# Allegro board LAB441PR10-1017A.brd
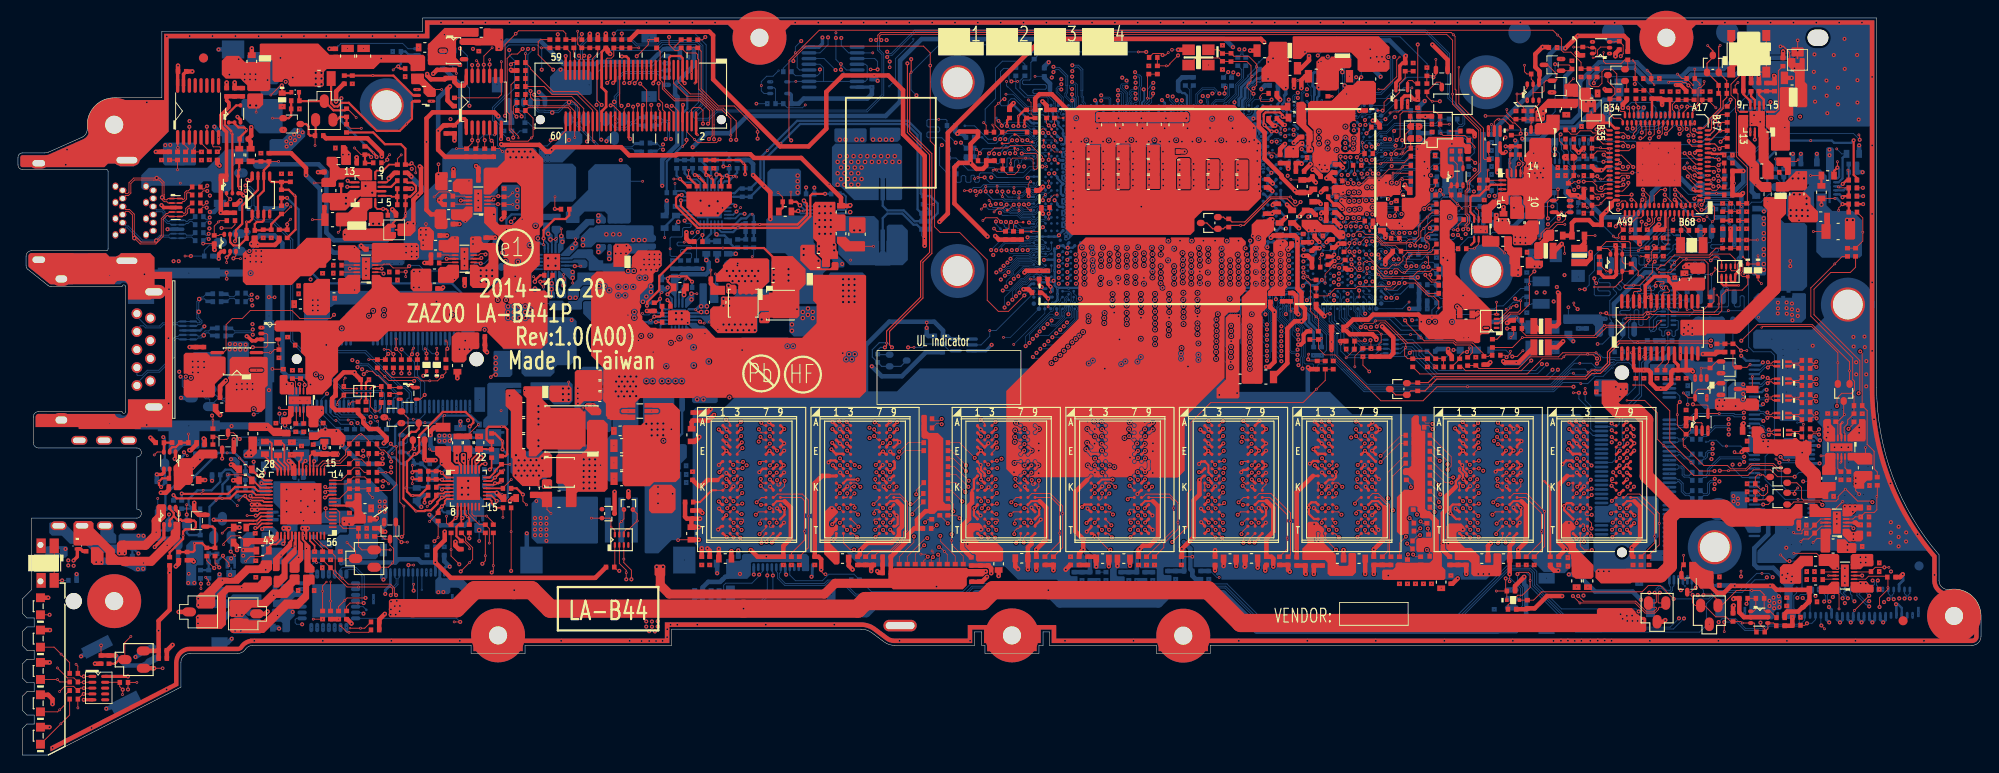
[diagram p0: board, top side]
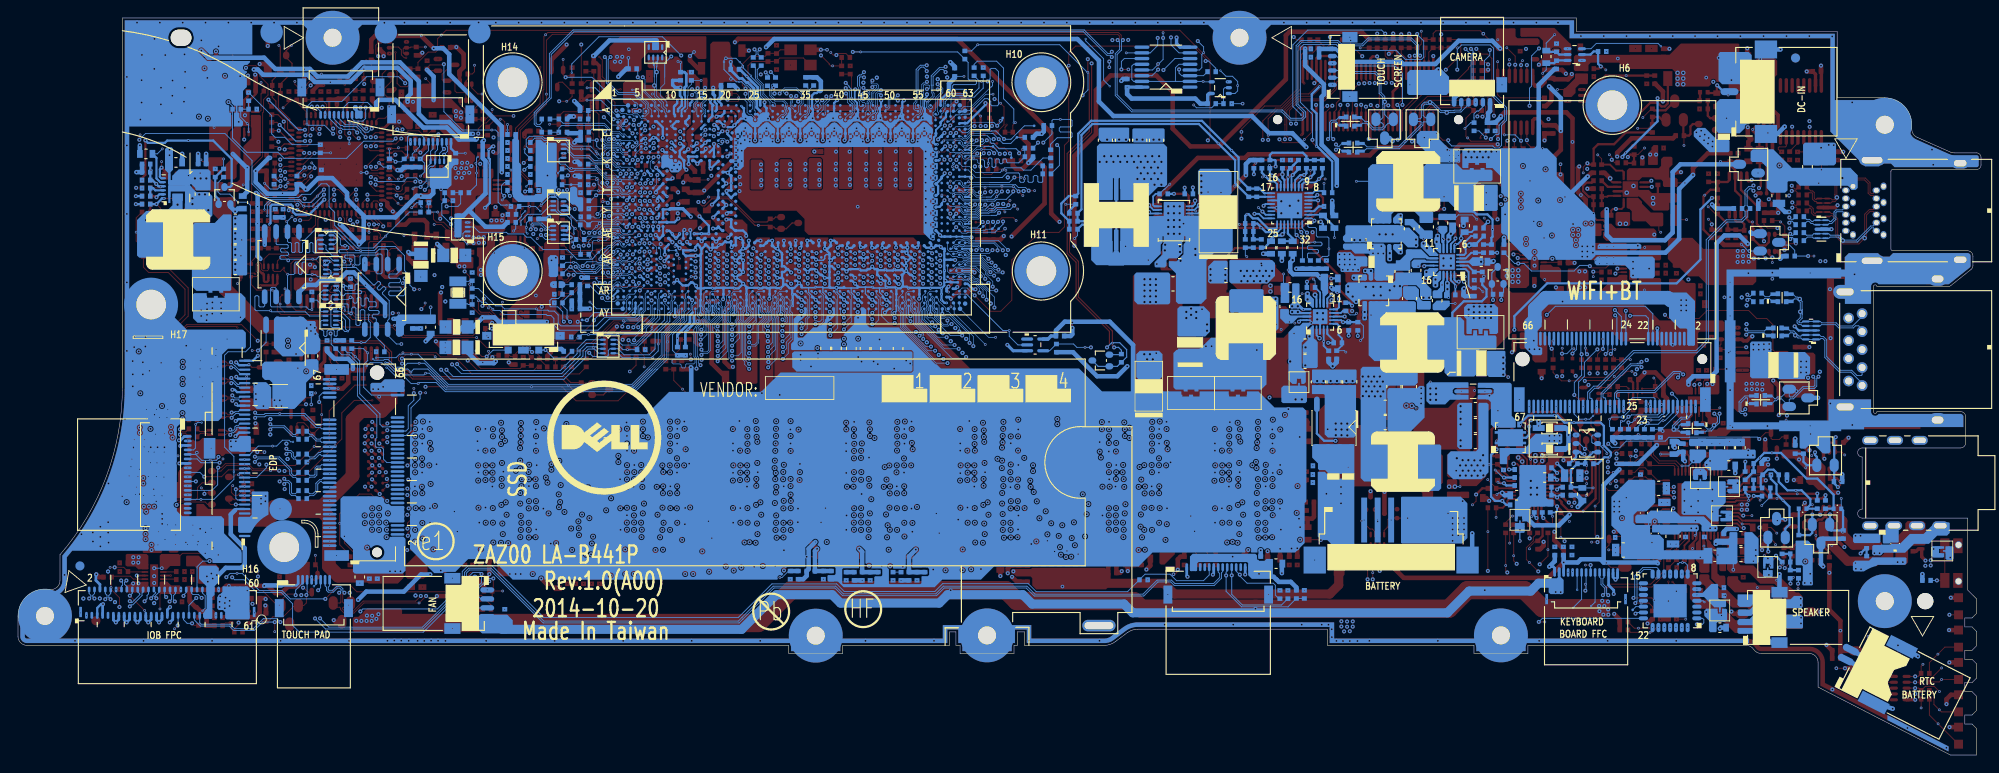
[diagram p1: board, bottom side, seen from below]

Outline 218.31 x 82 mm; copper layers: TOP, GND1, IN1, GND2, IN2, IN3, VCC, IN4, GND3, BOTTOM. Coordinates in mm from the lower left corner of the outline.
Outline path: 0,66.49 arc(0.15,66.84) 0.5,66.99 2.99,66.99 arc(3.2,67.01) 3.39,67.08 7.11,68.73 arc(7.54,69.09) 7.7,69.64 7.7,70.12 arc(8.58,72.24) 10.7,73.12 16,73.12 16,80.5 45,80.5 45,82 206.7,82 206.7,40.92 arc(208.49,30.98) 213.64,22.28 213.64,19.41 arc(213.99,18.65) 214.81,18.43 arc(217.25,17.76) 218.31,15.47 218.31,13.2 arc(218.02,12.49) 217.31,12.2 132.59,12.2 132.59,11.3 126.59,11.3 126.59,12.2 114.7,12.2 114.7,13.7 114,13.7 114,12.2 113.54,12.2 113.54,11.3 107.54,11.3 107.54,12.2 107.18,12.2 107.18,13.7 106.38,13.7 106.38,12.2 97.49,12.2 arc(96.86,12.3) 96.29,12.6 94.96,13.6 arc(94.39,13.9) 93.76,14 72.7,14 72.7,12.2 56.39,12.2 56.39,11.3 50.39,11.3 50.39,12.2 26.12,12.2 arc(25.64,12.08) 25.28,11.75 arc(24.92,11.42) 24.44,11.3 19.12,11.3 arc(18.41,11.01) 18.12,10.3 18.12,7.56 3.4,0 0.5,0 0.5,2.95 1,3.45 1.8,3.45 1.8,4.45 1,4.45 0.5,4.95 0.5,6.55 1,7.05 1.8,7.05 1.8,8.05 1,8.05 0.5,8.55 0.5,10.15 1,10.65 1.8,10.65 1.8,11.65 1,11.65 0.5,12.15 0.5,13.75 1,14.25 1.8,14.25 1.8,15.25 1,15.25 0.5,15.75 0.5,17.38 1.5,18.38 1.5,26.36 13.22,26.36 arc(13.72,26.86) 13.22,27.36 13.22,33.16 arc(13.72,33.66) 13.22,34.16 2.3,34.16 arc(1.88,34.34) 1.7,34.76 1.7,37.61 arc(1.88,38.03) 2.3,38.21 11.57,38.21 arc(11.77,38.01) 11.97,38.21 11.97,52.11 arc(11.77,52.31) 11.57,52.11 3.68,52.11 arc(3.51,52.14) 3.36,52.22 1.09,54.04 arc(0.95,54.21) 0.9,54.43 0.9,55.5 arc(1.08,55.93) 1.5,56.1 9.82,56.1 arc(9.96,56.16) 10.02,56.3 10.02,64.94 arc(9.96,65.08) 9.82,65.14 0.5,65.14 arc(0.15,65.29) 0,65.64 0,66.49

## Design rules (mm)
constraint set DEFAULT: min track width 0.102
net group 20: nets +RTCVCC N48756972
net group CLK_TP: nets CLK_TP_SIO DAT_TP_SIO
net group DDR-RESET: nets DDR3_DRAMRST# H_DRAMRST#
net group DDRA-CKE: nets DDR_A_CKE0 DDR_A_CKE1
net group DDRB-CKE: nets DDR_B_CKE0 DDR_B_CKE1
net group DIFFPAIR5: nets DMIC_CLK_CODEC DMIC_DAT_CODEC
net group DIFFPAIR23: nets CLK_SMB DAT_SMB
net group DIFFPAIR27: nets PCH_SMBCLK PCH_SMBDATA
net group DIFFPAIR44: nets SML1_SMBCLK SML1_SMBDAT
net group DMI_RCOMP: nets PCH_OPIRCOMP PROC_OPI_COMP
net group HOST-CLK: nets CLK_PCIE_MSATA CLK_PCIE_MSATA#
net group SML0CLK: nets SML0CLK SML0DATA
net group 5: nets CPU_XDP_TDI CPU_XDP_TDO CPU_XDP_TMS CPU_XDP_TRST# DSWODVREN PCH_DPWROK PCH_INTVRMEN PCH_JTAG_TCK PCH_JTAG_TDI PCH_JTAG_TDO PCH_JTAG_TMS PCH_RSMRST# SYS_PWROK SYS_RESET#
net group 8: nets 1.05VS_VCCST_PG H_CATERR# H_PROCHOT# H_PROCHOT#_R XDP_BPM1#
net group 12: nets +V1.05S_ASATA3PLL +V1.05S_AUSB3PLL PCIE_RCOMP SATA_RCOMP
net group 15: nets DISP_CLK_AUXP_CONN DISP_DAT_AUXN_CONN PCH_DP_CLK PCH_DP_DAT PCH_RTCRST# PCH_RTCX1 PCH_RTCX2 PCH_SRTCRST# SDIO_CLK SUSCLK
net group 18: nets CLK_LPC_DEBUG CLK_PCI_MEC CLK_PCIE_MMI CLK_PCIE_MMI# CLK_PCIE_WLAN CLK_PCIE_WLAN# CLKOUT_LPC0 CLKOUT_LPC1 EDP_AUXN EDP_AUXN_C EDP_AUXN_CONN EDP_AUXP EDP_AUXP_C EDP_AUXP_CONN EDP_TXN_P0 EDP_TXN_P0_C EDP_TXN_P0_CONN EDP_TXN_P1_C EDP_TXN_P1_CONN EDP_TXN_P2 EDP_TXN_P2_C EDP_TXN_P2_CONN EDP_TXN_P3 EDP_TXN_P3_C EDP_TXN_P3_CONN EDP_TXP_P0 EDP_TXP_P0_C EDP_TXP_P0_CONN EDP_TXP_P1_C EDP_TXP_P1_CONN EDP_TXP_P2 EDP_TXP_P2_C EDP_TXP_P2_CONN EDP_TXP_P3 EDP_TXP_P3_C EDP_TXP_P3_CONN H_CPU_SVIDALRT# H_CPU_SVIDCLK H_CPU_SVIDDAT PCH_DP_AUXN PCH_DP_AUXN_C PCH_DP_AUXP PCH_DP_AUXP_C PCH_DP_N0_C PCH_DP_N1 PCH_DP_N1_C PCH_DP_N2_C PCH_DP_N3 PCH_DP_N3_C PCH_DP_P0_C PCH_DP_P1 PCH_DP_P1_C PCH_DP_P2_C PCH_DP_P3 PCH_DP_P3_C PCIE_PRX_CARDTX_N1 PCIE_PRX_CARDTX_P1 PCIE_PRX_WLANTX_N4 PCIE_PRX_WLANTX_P4 PCIE_PTX_C_CARDRX_N1 PCIE_PTX_C_CARDRX_P1 PCIE_PTX_CARDRX_N1 PCIE_PTX_CARDRX_P1 PCIE_PTX_WLANRX_N4 PCIE_PTX_WLANRX_N4_C PCIE_PTX_WLANRX_P4 PCIE_PTX_WLANRX_P4_C SATA_RN2/PERN6_L1 SATA_RN2/PERN6_L1_C SATA_RN3/PERN6_L0_C SATA_RP2/PERP6_L1 SATA_RP2/PERP6_L1_C SATA_RP3/PERP6_L0_C SATA_TN2/PETN6_L1 SATA_TN2/PETN6_L1_C SATA_TN3/PETN6_L0_C SATA_TP2/PETP6_L1 SATA_TP2/PETP6_L1_C SATA_TP3/PETP6_L0_C USB3TN1 USB3TP1 USB20_N0 USB20_N1 USB20_N1_CONN USB20_N2 USB20_N2_R USB20_N3 USB20_N3_CONN USB20_N4 USB20_N4_CONN USB20_P0 USB20_P1 USB20_P1_CONN USB20_P2 USB20_P2_R USB20_P3 USB20_P3_CONN USB20_P4 USB20_P4_CONN USBRBIAS XTAL24_IN XTAL24_OUT
net group 25: nets EDP_COM
net group ASYNCHRONOUS: nets H_THERMTRIP# NGFF_RST# PCH_PLTRST# PCH_PLTRST#_EC PLTRST#_XDP RESET_OUT# THERMATRIP2# XDP_BPM0# XDP_PWRGD
net group DDR-DQS: nets DDR_A_DQS0 DDR_A_DQS1 DDR_A_DQS2 DDR_A_DQS3 DDR_A_DQS4 DDR_A_DQS5 DDR_A_DQS6 DDR_A_DQS7 DDR_A_DQS#0 DDR_A_DQS#1 DDR_A_DQS#2 DDR_A_DQS#3 DDR_A_DQS#4 DDR_A_DQS#5 DDR_A_DQS#6 DDR_A_DQS#7 DDR_B_DQS0 DDR_B_DQS1 DDR_B_DQS2 DDR_B_DQS3 DDR_B_DQS4 DDR_B_DQS5 DDR_B_DQS6 DDR_B_DQS7 DDR_B_DQS#0 DDR_B_DQS#1 DDR_B_DQS#2 DDR_B_DQS#3 DDR_B_DQS#4 DDR_B_DQS#5 DDR_B_DQS#6 DDR_B_DQS#7
net group DDR-SINGLE: nets SM_RCOMP0 SM_RCOMP1 SM_RCOMP2
net group DDRA-CMD: nets DDR_A_BA0 DDR_A_BA1 DDR_A_BA2 DDR_A_CAS# DDR_A_MA0 DDR_A_MA1 DDR_A_MA2 DDR_A_MA3 DDR_A_MA4 DDR_A_MA5 DDR_A_MA6 DDR_A_MA7 DDR_A_MA8 DDR_A_MA9 DDR_A_MA10 DDR_A_MA11 DDR_A_MA12 DDR_A_MA13 DDR_A_MA14 DDR_A_MA15 DDR_A_RAS# DDR_A_WE#
net group DDRA-CTL: nets DDR_A_CS0# DDR_A_CS1# M_ODT0
net group DDRA-D0: nets DDR_A_D0 DDR_A_D1 DDR_A_D2 DDR_A_D3 DDR_A_D4 DDR_A_D5 DDR_A_D6 DDR_A_D7
net group DDRA-D1: nets DDR_A_D8 DDR_A_D9 DDR_A_D10 DDR_A_D11 DDR_A_D12 DDR_A_D13 DDR_A_D14 DDR_A_D15
net group DDRA-D2: nets DDR_A_D16 DDR_A_D17 DDR_A_D18 DDR_A_D19 DDR_A_D20 DDR_A_D21 DDR_A_D22 DDR_A_D23
net group DDRA-D3: nets DDR_A_D24 DDR_A_D25 DDR_A_D26 DDR_A_D27 DDR_A_D28 DDR_A_D29 DDR_A_D30 DDR_A_D31
net group DDRA-D4: nets DDR_A_D32 DDR_A_D33 DDR_A_D34 DDR_A_D35 DDR_A_D36 DDR_A_D37 DDR_A_D38 DDR_A_D39
net group DDRA-D5: nets DDR_A_D40 DDR_A_D41 DDR_A_D42 DDR_A_D43 DDR_A_D44 DDR_A_D45 DDR_A_D46 DDR_A_D47
net group DDRA-D6: nets DDR_A_D48 DDR_A_D49 DDR_A_D50 DDR_A_D51 DDR_A_D52 DDR_A_D53 DDR_A_D54 DDR_A_D55
net group DDRA-D7: nets DDR_A_D56 DDR_A_D57 DDR_A_D58 DDR_A_D59 DDR_A_D60 DDR_A_D61 DDR_A_D62 DDR_A_D63
net group DDRB-CMD: nets DDR_B_BA0 DDR_B_BA1 DDR_B_BA2 DDR_B_CAS# DDR_B_MA0 DDR_B_MA1 DDR_B_MA2 DDR_B_MA3 DDR_B_MA4 DDR_B_MA5 DDR_B_MA6 DDR_B_MA7 DDR_B_MA8 DDR_B_MA9 DDR_B_MA10 DDR_B_MA11 DDR_B_MA12 DDR_B_MA13 DDR_B_MA14 DDR_B_MA15 DDR_B_RAS# DDR_B_WE#
net group DDRB-CTL: nets DDR_B_CS0# DDR_B_CS1# M_ODT2
net group DDRB-D0: nets DDR_B_D0 DDR_B_D1 DDR_B_D2 DDR_B_D3 DDR_B_D4 DDR_B_D5 DDR_B_D6 DDR_B_D7
net group DDRB-D1: nets DDR_B_D8 DDR_B_D9 DDR_B_D10 DDR_B_D11 DDR_B_D12 DDR_B_D13 DDR_B_D14 DDR_B_D15
net group DDRB-D2: nets DDR_B_D16 DDR_B_D17 DDR_B_D18 DDR_B_D19 DDR_B_D20 DDR_B_D21 DDR_B_D22 DDR_B_D23
net group DDRB-D3: nets DDR_B_D24 DDR_B_D25 DDR_B_D26 DDR_B_D27 DDR_B_D28 DDR_B_D29 DDR_B_D30 DDR_B_D31
net group DDRB-D4: nets DDR_B_D32 DDR_B_D33 DDR_B_D34 DDR_B_D35 DDR_B_D36 DDR_B_D37 DDR_B_D38 DDR_B_D39
net group DDRB-D5: nets DDR_B_D40 DDR_B_D41 DDR_B_D42 DDR_B_D43 DDR_B_D44 DDR_B_D45 DDR_B_D46 DDR_B_D47
net group DDRB-D6: nets DDR_B_D48 DDR_B_D49 DDR_B_D50 DDR_B_D51 DDR_B_D52 DDR_B_D53 DDR_B_D54 DDR_B_D55
net group DDRB-D7: nets DDR_B_D56 DDR_B_D57 DDR_B_D58 DDR_B_D59 DDR_B_D60 DDR_B_D61 DDR_B_D62 DDR_B_D63
net group DIFFPAIR39: nets I2C1_SDA
net group ESD-NOCROSS-MOAT: nets CFG0 CFG1 CFG2 CFG3 CFG4 CFG5 CFG6 CFG7 CFG8 CFG9 CFG10 CFG11 CFG12 CFG13 CFG14 CFG15 CFG16 CFG17 CFG18 CFG19 MPCIE_RST# PCH_JTAG_TRST# SUSACK# USB_OC0# USB_OC1# USB_OC2#
net group I2C0_SCK_DSP: nets I2C0_SDA_DSP
net group I2C_6_18: nets I2C0_SCK I2C0_SCK_DSP I2C0_SDA I2C1_SCK
net group I2S: nets I2S_BIT_CLK I2S_BITCLK_AUDIO I2S_BITCLK_AUDIO_R I2S_RST# I2S_RST_AUDIO# I2S_RST_AUDIO#_R I2S_SDIN0 I2S_SDIN0_AUDIO I2S_SDOUT I2S_SDOUT_AUDIO I2S_SDOUT_AUDIO_R I2S_SYNC I2S_SYNC_AUDIO I2S_SYNC_AUDIO_R
net group PWR: nets +0.675VS +0.675VSP +1.5V_B+ +1.05VDX_MODPHY_D +1.5VS +1.05VS_VCCST +1.05VSP +1.5VSP +1.8VS +1.8VSP +1.35V_DDR +3.3VDX_SSD +3V_NFC +3V_PCH +3V_PCH_DSW +3VALWP +3VLP +3VS_AUDIO +3VS_CAM +3VS_CR +3VS_TP +3VS_TPM +3VS_TS +5V_USB_P1 +5VALWP +5VS +5VS_AUDIO +AVDD1 +DVDD +DVDDIO +INV_PWR_SRC +LCDVDD +MD_VREF_CA +MD_VREF_DQA +MD_VREF_DQB +PCH_VCCDSW +RTC_VCCSUS +RTCBATT +V1.05S_APLLOPI +V1.05S_AXCK_DCB +V1.05S_AXCK_DCB_L +V1.05S_AXCK_LCPLL +V1.05S_AXCK_LCPLL_L +V1.05VS_VCCHSIO +VCCIO_OUT +VCCIOA_OUT +VS_LPSS_SDIO
net group SATA: nets SATA_RN3/PERN6_L0 SATA_RP3/PERP6_L0 SATA_TN3/PETN6_L0 SATA_TP3/PETP6_L0
net group SDIO_6_18: nets SDIO_CMD SDIO_D0 SDIO_D1 SDIO_D2 SDIO_D3
net group SENSE: nets VCCSENSE VCCSENSE_R VSSSENSE
net group SPI: nets PCH_SPI_CLK PCH_SPI_CLK_TPM PCH_SPI_CS0# PCH_SPI_CS1# PCH_SPI_CS2# PCH_SPI_IO2 PCH_SPI_IO3 PCH_SPI_SI PCH_SPI_SI_TPM PCH_SPI_SO PCH_SPI_SO_TPM SPI_CLK_ROM SPI_CLK_VROM SPI_IO2_ROM SPI_IO2_VROM SPI_IO3_ROM SPI_IO3_VROM SPI_SI_ROM SPI_SI_VROM SPI_SO_ROM SPI_SO_VROM
net group SVID: nets VR_SVID_ALRT# VR_SVID_CLK VR_SVID_DAT
net group UART_6_18: nets UART1_CTS# UART1_CTS#_NGFF UART1_RTS# UART1_RTS#_NGFF UART1_RXD UART1_RXD_NGFF UART1_TXD UART1_TXD_NGFF
net group USB30: nets USB3RN0 USB3RN1 USB3RN1_RC_CON USB3RP0 USB3RP1 USB3RP1_RC_CON USB3TN0 USB3TN1_C USB3TN1_RC_CON USB3TP0 USB3TP1_C USB3TP1_RC_CON
nets with their own width: min track width 0.102; nets JACK_PLUG_DL# NB_MUTE#
nets with their own width: min track width 0.127; nets REM_DIODE1_N REM_DIODE1_P REM_DIODE2_N REM_DIODE2_P REM_DIODE3_N REM_DIODE3_P REM_DIODE4_N REM_DIODE4_P
nets with their own width: min track width 0.254; nets +3.3V_ALW_DEG +RTC_CELL_VBAT MIC1-VREFO
nets with their own width: min track width 0.381; nets CFG_RCOMP
nets with their own width: min track width 0.508; nets +1.05VS +1.8VS_AUDIO +3.3V_M +3V_ROM +3VALW_5085 +VCC_CORE AGND B+ GND GNDA_CHG N45904045 N49757206 V_DDR_REF_CA
nets with their own width: min track width 1.016; nets MIC1_L_L MIC1_R_L SPK_L+_C SPK_L-_C SPK_OUT_L+ SPK_OUT_L- SPK_OUT_R+ SPK_OUT_R- SPK_R+_C SPK_R-_C
nets with their own width: min track width 1.524; nets +1.05VDX_MODPHY
nets with their own width: min track width 2.032; nets +3VS_NGFF

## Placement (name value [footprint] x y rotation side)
C1  .47U_0402_10V6K  [C_0402]  139.29 51.33 270 top
C2  15P_0402_50V8J  [C_0402]  23.39 40.66 180 top
C3  15P_0402_50V8J  [C_0402]  19.77 44.47 90 top
C4  15P_0402_50V8J  [C_0402]  54.03 70.35 270 bottom
C5  15P_0402_50V8J  [C_0402]  73.61 78.56 0 bottom
C6  15P_0402_50V8J  [C_0402]  193.21 33.97 180 top
C7  15P_0402_50V8J  [C_0402]  188.31 18.88 0 top
C8  2.2U_0603_6.3V6K~D  [C_0603]  45.95 78.72 180 top
C218  2200P_0402_25V7K  [C_0402]  161.07 56.33 180 top
C219  0.1U_0402_10V7K  [C_0402]  166.91 55.94 0 top
C265  .1U_0402_16V7K~D  [C_0402]  20.66 44.47 90 top
C303  150U_B2_6.3VM_R35M  [C_B2]  21.71 43.38 180 bottom
C352  0.1U_0402_10V7K  [C_0402]  45.74 51.89 0 top
C355  2200P_0402_25V7K~D  [C_0402]  46.84 54.75 180 top
C375  0.1U_0402_25V6K~D  [C_0402]  46.45 22.25 90 bottom
C376  0.1U_0402_25V6K~D  [C_0402]  47.4 22.25 90 bottom
C377  0.1U_0402_25V6K~D  [C_0402]  45.5 22.25 90 bottom
C612  0.1U_0402_25V6K~D  [C_0402]  186.61 41.1 180 bottom
C613  0.1U_0402_25V6K~D  [C_0402]  188.94 44.83 90 top
C621  0.1U_0402_10V7K  [C_0402]  25.32 50.43 180 bottom
C623  0.1U_0402_10V7K  [C_0402]  25.32 51.39 180 bottom
C712  22U_0603_6.3V6M~D  [C_0603]  32.11 50.17 180 top
C713  0.1U_0402_10V7K  [C_0402]  51.01 46.55 0 top
C715  0.1U_0402_10V7K  [C_0402]  32.12 52.2 180 top
C716  22U_0603_6.3V6M~D  [C_0603]  48.86 44.04 270 top
C719  4.7U_0603_6.3V6K  [C_0603]  180.29 20.52 270 bottom
C720  .1U_0402_16V7K~D  [C_0402]  176.45 41.35 180 top
C721  0.01U_0402_16V7K~D  [C_0402]  176.45 40.4 180 top
C722  47P_0402_50V8J~D  [C_0402]  179.24 20.54 270 bottom
C723  4.7U_0603_6.3V6K  [C_0603]  185.32 52.21 90 top
C962  10U_0603_6.3V6M~D  [C_0603]  23.37 38.63 180 top
C963  .1U_0402_16V7K~D  [C_0402]  23.39 39.77 180 top
C1060  0.1U_0402_10V7K  [C_0402]  199.31 37.3 180 top
C1061  0.1U_0402_10V7K  [C_0402]  199.31 39.21 180 top
C1062  0.1U_0402_10V7K  [C_0402]  199.31 38.19 180 top
C1063  0.1U_0402_10V7K  [C_0402]  199.31 40.1 180 top
C1064  0.1U_0402_10V7K  [C_0402]  199.31 36.29 180 top
C1065  0.1U_0402_10V7K  [C_0402]  199.31 35.4 180 top
C1066  0.1U_0402_10V7K  [C_0402]  199.31 42 180 top
C1067  0.1U_0402_10V7K  [C_0402]  199.31 41.11 180 top
C1068  0.1U_0402_10V7K  [C_0402]  199.31 43.91 180 top
C1069  0.1U_0402_10V7K  [C_0402]  199.31 43.02 180 top
C1102  0.1U_0402_25V6K~D  [C_0402]  164.18 16.21 270 bottom
C1134  0.1U_0402_10V7K  [C_0402]  80.1 21.17 90 bottom
C1137  2200P_0402_25V7K~D  [C_0402]  185.51 42.83 270 top
C1138  2200P_0402_25V7K~D  [C_0402]  180.81 42.83 270 top
C1139  2200P_0402_25V7K~D  [C_0402]  179.93 42.83 270 top
C1140  0.1U_0402_10V7K  [C_0402]  184.24 52.2 90 top
C1141  0.1U_0402_10V7K  [C_0402]  183.94 45.21 90 bottom
C1142  2200P_0402_25V7K~D  [C_0402]  184.62 42.83 270 top
C1143  10U_0603_6.3V6M~D  [C_0603]  193.2 36.07 180 top
C1145  .1U_0402_16V7K~D  [C_0402]  193.21 34.93 180 top
C1158  1U_0402_6.3V6K~D  [C_0402]  204.93 27.51 0 top
C1159  0.1U_0402_10V7K  [C_0402]  199.15 17.05 0 top
C1160  1U_0402_6.3V6K~D  [C_0402]  41.29 52.85 0 top
C1161  0.1U_0402_10V7K  [C_0402]  204.18 23.2 0 top
C1162  1U_0402_6.3V6K~D  [C_0402]  204.93 24.59 0 top
C1163  2200P_0402_25V7K~D  [C_0402]  199.8 24.69 180 top
C1164  0.1U_0402_10V7K  [C_0402]  197.13 25.89 0 top
C1165  1U_0402_6.3V6K~D  [C_0402]  201.26 37.09 90 top
C1166  1U_0402_6.3V6K~D  [C_0402]  39.67 56.28 180 top
C1167  2200P_0402_25V7K~D  [C_0402]  35.98 53.61 180 top
C1169  1U_0402_6.3V6K~D  [C_0402]  29.51 42.01 90 top
C1199  1U_0402_6.3V6K~D  [C_0402]  52.04 56.64 90 top
C1200  0.1U_0402_10V7K  [C_0402]  45.99 57.8 0 top
C1201  1U_0402_6.3V6K~D  [C_0402]  50.59 52.91 180 top
C1202  2200P_0402_25V7K~D  [C_0402]  48.37 61.23 180 top
C1203  1U_0402_6.3V6K~D  [C_0402]  52.11 64.91 180 top
C1204  1U_0402_6.3V6K~D  [C_0402]  52.11 63.96 180 top
C1208  0.1U_0402_10V7K  [C_0402]  47.52 64.47 0 top
C1209  10U_0603_6.3V6M~D  [C_0603]  172.19 72.63 270 top
C1211  0.1U_0402_10V7K  [C_0402]  200.99 28.78 0 top
C1212  1000P_0402_50V7K~D  [C_0402]  31.78 36.88 270 top
C1213  1U_0402_6.3V6K~D  [C_0402]  31.74 45.6 180 top
C1214  4700P_0402_25V7K  [C_0402]  30.89 36.88 270 top
C1215  0.1U_0402_10V7K  [C_0402]  34.31 50.81 0 top
C1216  0.1U_0402_10V7K  [C_0402]  33.88 54.51 270 top
C1217  0.1U_0402_10V7K  [C_0402]  28.68 36 90 top
C1218  0.1U_0402_10V7K  [C_0402]  33.94 36.02 90 top
C1219  0.1U_0402_10V7K  [C_0402]  205 29.99 0 top
C1220  0.1U_0402_10V7K  [C_0402]  47.45 59.07 0 top
C1221  1U_0402_6.3V6K~D  [C_0402]  54.92 70.35 270 bottom
C1222  1U_0402_6.3V6K~D  [C_0402]  73.61 77.64 0 bottom
C1223  1U_0402_6.3V6K~D  [C_0402]  51.25 79.22 270 top
C1224  1U_0402_6.3V6K~D  [C_0402]  163.06 60.83 90 top
C1225  1U_0402_6.3V6K~D  [C_0402]  188.31 19.82 0 top
C1227  0.01U_0402_16V7K~D  [C_0402]  166.59 70.74 90 top
C1228  0.1U_0402_10V7K  [C_0402]  170.32 65.36 0 top
C1230  2200P_0402_25V7K~D  [C_0402]  203.61 31.52 270 top
C1231  1U_0402_6.3V6K~D  [C_0402]  205.1 37.06 90 top
C1237  0.1U_0402_10V7K  [C_0402]  56.43 74.37 180 top
C1240  10U_0603_6.3V6M~D  [C_0603]  165.21 58.81 90 top
C1241  0.1U_0402_10V7K~D  [C_0402]  163.42 63.07 180 top
C1242  0.01U_0402_16V7K~D  [C_0402]  163.43 63.96 180 top
C1243  0.1U_0402_10V7K~D  [C_0402]  170.32 64.47 0 top
C1244  1000P_0402_25V8J  [C_0402]  166.08 66.8 90 top
C1247  2200P_0402_25V7K~D  [C_0402]  202.72 31.52 270 top
C1254  1U_0402_6.3V6K~D  [C_0402]  206.09 18.44 0 top
C1256  1U_0402_6.3V6K~D  [C_0402]  206.09 21.38 0 top
C1257  2200P_0402_25V7K~D  [C_0402]  200.7 19.52 180 top
C1258  2200P_0402_25V7K~D  [C_0402]  200.7 20.41 180 top
C1264  0.1U_0402_10V7K  [C_0402]  198.01 20.41 0 top
C1273  0.1U_0402_16V7K~D  [C_0402]  36.21 67.53 180 top
C1274  0.1U_0402_16V7K~D  [C_0402]  159.35 19.06 90 top
C1275  0.1U_0402_16V7K~D  [C_0402]  170.25 78.71 0 top
C1278  220P_0402_25V8K  [C_0402]  46.84 55.64 180 top
C1281  2200P_0402_25V7K~D  [C_0402]  48.37 62.18 180 top
C1282  0.1U_0402_10V7K  [C_0402]  63.59 78.68 90 top
C1283  0.1U_0402_10V7K  [C_0402]  38.7 39.29 270 top
C1284  0.1U_0402_10V7K  [C_0402]  38.12 41.76 0 top
C1285  0.1U_0402_10V7K  [C_0402]  47.59 75.31 90 top
C1286  0.1U_0402_10V7K  [C_0402]  48.54 70.07 270 top
C1289  0.1U_0402_10V7K  [C_0402]  29.99 47.41 270 top
C1292  2200P_0402_25V7K~D  [C_0402]  199.8 25.58 180 top
C1293  2200P_0402_25V7K~D  [C_0402]  35.98 54.5 180 top
C1297  15P_0402_50V8J  [C_0402]  32.12 51.31 180 top
C1298  15P_0402_50V8J  [C_0402]  51.02 45.6 0 top
C1299  15P_0402_50V8J  [C_0402]  47.59 70.07 270 top
C1300  15P_0402_50V8J  [C_0402]  48.54 75.31 90 top
C1301  15P_0402_50V8J  [C_0402]  26.57 60.8 0 bottom
C1302  15P_0402_50V8J  [C_0402]  25.68 60.8 180 bottom
C1304  15P_0402_50V8J  [C_0402]  178.35 20.54 270 bottom
C1309  15P_0402_50V8J  [C_0402]  15.64 11.63 0 top
C1312  22U_0805_6.3V6M  [C_0805]  139.5 78.37 180 top
C1313  22U_0805_6.3V6M  [C_0805]  140.59 76.4 0 top
C1314  22U_0805_6.3V6M  [C_0805]  145.22 75.52 180 top
C1315  22U_0805_6.3V6M  [C_0805]  146.37 75.52 0 top
C1321  1U_0402_6.3V6K~D  [C_0402]  204.93 25.6 0 top
C1322  0.1U_0402_10V7K  [C_0402]  196.7 16.6 90 top
C1324  0.1U_0402_10V7K  [C_0402]  197.32 15.33 0 top
C1325  1U_0402_6.3V6K~D  [C_0402]  198.01 19.52 0 top
C2973  0.1U_0402_16V4Z  [C_0402]  9.24 11.08 270 top
C2982  0.1U_0402_25V6K~D  [C_0402]  186.61 40.21 180 bottom
C2983  0.1U_0402_10V7K  [C_0402]  5.61 19.43 0 bottom
C2985  47U_1210_16V6M  [C_1210]  187.8 39.96 0 bottom
CA2  10U_0805_10V6K  [C_0805]  35.21 26.4 90 bottom
CA3  0.1U_0402_16V7K~N  [C_0402]  30.76 25.17 270 bottom
CA4  10U_0805_10V6K  [C_0805]  36.69 29.67 180 bottom
CA5  0.1U_0402_16V7K~N  [C_0402]  37.88 30.29 90 bottom
CA23  10P_0402_50V8J~D  [C_0402]  33.84 20.84 0 top
CA24  10P_0402_50V8J~D  [C_0402]  37.76 31.45 180 top
CA25  10P_0402_50V8J~D  [C_0402]  34.76 21.72 90 top
CA26  10P_0402_50V8J~D  [C_0402]  37.76 32.4 180 top
CA27  10P_0402_50V8J~D  [C_0402]  37.76 34.62 180 top
CA28  100P_0402_50V8J~D  [C_0402]  7.56 23.58 270 top
CA29  100P_0402_50V8J~D  [C_0402]  20.26 23.55 90 bottom
CA31  0.1U_0402_10V7K  [C_0402]  36.86 27.84 270 top
CA33  100P_0402_50V8J~D  [C_0402]  21.21 22.39 180 bottom
CA34  0.1U_0402_10V7K  [C_0402]  22.13 22.39 270 bottom
CA40  0.1U_0402_25V6K~D  [C_0402]  18.96 34.76 0 top
CA42  4.7U_0603_6.3V6K  [C_0603]  37.88 27.45 0 top
CA48  10U_0603_6.3V6M~D  [C_0603]  34.19 33.48 90 bottom
CA49  0.1U_0402_10V7K  [C_0402]  33.11 33.72 90 bottom
CA53  1000P_0402_50V7K~D  [C_0402]  26.45 19.78 270 top
CA54  1000P_0402_50V7K~D  [C_0402]  31.16 18.3 180 top
CA55  1000P_0402_50V7K~D  [C_0402]  26.45 21.62 270 top
CA56  1000P_0402_50V7K~D  [C_0402]  32.94 18.3 180 top
CA57  0.1U_0402_10V7K  [C_0402]  36.85 30.49 0 top
CA68  100P_0402_50V8J~D  [C_0402]  10.56 23.83 270 bottom
CA69  100P_0402_50V8J~D  [C_0402]  15.31 24.98 270 bottom
CA70  4.7U_0402_6.3V6M  [C_0402]  24.35 28.8 180 bottom
CA71  4.7U_0402_6.3V6M  [C_0402]  26.22 29.67 180 bottom
CA74  10U_0603_6.3V6M~D  [C_0603]  18.7 30.59 0 top
CA78  0.1U_0402_10V7K  [C_0402]  29.05 33.72 90 bottom
CA80  0.1U_0402_10V7K  [C_0402]  29.94 33.72 90 bottom
CA82  10U_0603_6.3V6M~D  [C_0603]  27.97 33.48 90 bottom
CA83  10U_0603_6.3V6M~D  [C_0603]  26.76 33.48 90 bottom
CA84  2.2U_0603_6.3V6K~D  [C_0603]  26 31.78 180 top
CA85  2.2U_0603_6.3V6K~D  [C_0603]  26 30.56 180 top
CA86  0.1U_0402_10V7K  [C_0402]  26.38 23.75 90 top
CA87  2.2U_0603_6.3V6K~D  [C_0603]  25.37 23.64 180 top
CA88  0.1U_0402_10V7K  [C_0402]  31.53 33.47 90 top
CA90  10U_0603_6.3V6M~D  [C_0603]  30.46 33.4 90 top
CA91  0.1U_0402_10V7K  [C_0402]  32.1 33.72 90 bottom
CA92  4.7U_0603_6.3V6K  [C_0603]  31.02 33.48 90 bottom
CA93  10U_0603_6.3V6M~D  [C_0603]  27.91 22.75 180 top
CA94  10U_0603_6.3V6M~D  [C_0603]  25.38 25.31 180 top
CA95  2.2U_0603_6.3V6K~D  [C_0603]  28.92 34.75 270 top
CA96  2.2U_0603_6.3V6K~D  [C_0603]  27.46 34.88 270 top
CA97  0.1U_0402_16V7K~N  [C_0402]  39.77 24.21 0 bottom
CA98  10U_0805_10V6K  [C_0805]  38.93 22.81 0 bottom
CA99  10U_0805_10V6K  [C_0805]  34.26 25.19 270 bottom
CA100  0.1U_0402_16V7K~N  [C_0402]  32.86 25.17 270 bottom
CA101  10U_0805_10V6K  [C_0805]  27.55 24.08 180 bottom
CA102  10U_0805_10V6K  [C_0805]  27.55 22.3 180 bottom
CA103  0.1U_0402_16V7K~N  [C_0402]  28.6 23.69 90 bottom
CA104  0.1U_0402_10V7K  [C_0402]  32.83 33.63 90 top
CA105  4.7U_0603_6.3V6K  [C_0603]  34.07 33.48 90 top
CA106  0.1U_0402_10V7K  [C_0402]  36.86 29.62 270 top
CC160  10U_0603_6.3V6M~D  [C_0603]  120.43 45.94 270 bottom
CC161  10U_0603_6.3V6M~D  [C_0603]  122.9 45.95 270 bottom
CC162  10U_0603_6.3V6M~D  [C_0603]  124.11 45.95 270 bottom
CC163  10U_0603_6.3V6M~D  [C_0603]  125.63 45.94 270 bottom
CC164  10U_0603_6.3V6M~D  [C_0603]  127.28 45.95 270 bottom
CC165  10U_0603_6.3V6M~D  [C_0603]  128.49 45.95 270 bottom
CC233  2.2U_0402_6.3V6M~D  [C_0402]  131.92 45.4 270 bottom
CC234  2.2U_0402_6.3V6M~D  [C_0402]  130.59 45.4 270 bottom
CC238  2.2U_0402_6.3V6M~D  [C_0402]  121.51 45.41 270 bottom
CC239  2.2U_0402_6.3V6M~D  [C_0402]  119.35 45.43 270 bottom
CC240  0.1U_0402_10V7K  [C_0402]  102.88 46.62 180 bottom
CC243  15P_0402_50V8J  [C_0402]  104.35 65.55 180 bottom
CD5  0.1U_0402_25V6K~D  [C_0402]  146.27 42.93 90 top
CD35  .047U_0402_16V7K  [C_0402]  159.22 22.06 270 top
CD37  .047U_0402_16V7K  [C_0402]  129.38 22.06 270 top
CD39  0.022U_0402_16V7K~D  [C_0402]  131.54 19.56 90 bottom
CD40  1U_0402_6.3V6K~D  [C_0402]  161.07 22.06 270 top
CD41  10U_0603_6.3V6M~D  [C_0603]  164.49 21.86 0 top
CD42  1U_0402_6.3V6K~D  [C_0402]  160.18 22.06 270 top
CD43  0.022U_0402_16V7K~D  [C_0402]  125.32 19.43 90 bottom
CD44  1U_0402_6.3V6K~D  [C_0402]  144.11 22 270 top
CD45  10U_0603_6.3V6M~D  [C_0603]  162.08 21.86 0 top
CD46  1U_0402_6.3V6K~D  [C_0402]  133.13 22.06 270 top
CD47  10U_0603_6.3V6M~D  [C_0603]  136.47 21.87 0 top
CD50  10U_0603_6.3V6M~D  [C_0603]  134.08 21.86 0 top
CD51  .047U_0402_16V7K  [C_0402]  142.21 22 270 top
CD52  .047U_0402_16V7K  [C_0402]  171.35 22.06 270 top
CD54  1U_0402_6.3V6K~D  [C_0402]  145.06 22 270 top
CD55  10U_0603_6.3V6M~D  [C_0603]  148.43 21.86 0 top
CD56  1U_0402_6.3V6K~D  [C_0402]  143.16 22 270 top
CD57  10U_0603_6.3V6M~D  [C_0603]  146.02 21.86 0 top
CD58  1U_0402_6.3V6K~D  [C_0402]  173.28 21 180 top
CD59  10U_0603_6.3V6M~D  [C_0603]  174.6 20.08 270 top
CD60  1U_0402_6.3V6K~D  [C_0402]  173.28 21.96 180 top
CD61  10U_0603_6.3V6M~D  [C_0603]  173.33 20.08 270 top
CD66  1U_0402_6.3V6K~D  [C_0402]  75.02 26.29 90 top
CD67  10U_0603_6.3V6M~D  [C_0603]  74.9 25.35 270 top
CD68  1U_0402_6.3V6K~D  [C_0402]  75.06 38.1 270 top
CD69  10U_0603_6.3V6M~D  [C_0603]  74.92 34.9 90 top
CD70  1U_0402_6.3V6K~D  [C_0402]  76.93 22.06 270 top
CD71  10U_0603_6.3V6M~D  [C_0603]  90.99 21.86 0 top
CD72  1U_0402_6.3V6K~D  [C_0402]  76.04 22.06 270 top
CD73  10U_0603_6.3V6M~D  [C_0603]  77.94 21.86 0 top
CD76  0.022U_0402_16V7K~D  [C_0402]  120.11 19.43 90 bottom
CD77  .047U_0402_16V7K  [C_0402]  75.02 30.61 90 top
CD78  .047U_0402_16V7K  [C_0402]  88.61 22.06 270 top
CD79  1U_0402_6.3V6K~D  [C_0402]  107.92 22 270 top
CD80  10U_0603_6.3V6M~D  [C_0603]  110.91 21.9 0 top
CD81  10U_0603_6.3V6M~D  [C_0603]  109.06 21.99 270 top
CD82  1U_0402_6.3V6K~D  [C_0402]  107.03 22 270 top
CD83  10U_0603_6.3V6M~D  [C_0603]  122.27 21.86 0 top
CD84  1U_0402_6.3V6K~D  [C_0402]  118.97 22.06 270 top
CD85  .047U_0402_16V7K  [C_0402]  85.12 22.06 270 top
CD86  10U_0603_6.3V6M~D  [C_0603]  119.92 21.86 0 top
CD87  .047U_0402_16V7K  [C_0402]  93.37 22.06 270 top
CD88  .047U_0402_16V7K  [C_0402]  113.25 22.06 270 top
CD89  .047U_0402_16V7K  [C_0402]  124.62 22.06 270 top
CD90  .047U_0402_16V7K  [C_0402]  166.84 22.06 270 top
CD91  .047U_0402_16V7K  [C_0402]  138.84 22.06 270 top
CD92  1U_0402_6.3V6K~D  [C_0402]  117.06 21.15 90 top
CD93  .047U_0402_16V7K  [C_0402]  106.01 22 270 top
CD94  .047U_0402_16V7K  [C_0402]  118.01 22.06 270 top
CD95  .047U_0402_16V7K  [C_0402]  150.78 22.06 270 top
CD96  .047U_0402_16V7K  [C_0402]  179.61 22.06 270 top
CD101  10U_0603_6.3V6M~D  [C_0603]  158.27 19.95 270 top
CD129  1U_0402_6.3V6K~D  [C_0402]  156.3 19.97 270 top
CD132  1U_0402_6.3V6K~D  [C_0402]  155.41 19.97 270 top
CD133  1U_0402_6.3V6K~D  [C_0402]  154.53 19.97 270 top
CD135  1U_0402_6.3V6K~D  [C_0402]  157.19 19.97 270 top
CD136  1U_0402_6.3V6K~D  [C_0402]  97.07 21.16 180 top
CD139  1U_0402_6.3V6K~D  [C_0402]  97.07 22.05 180 top
CD140  1U_0402_6.3V6K~D  [C_0402]  97.07 20.27 180 top
CD142  1U_0402_6.3V6K~D  [C_0402]  106.94 20.19 270 top
CD143  15P_0402_50V8J  [C_0402]  153.64 19.97 270 top
CD144  15P_0402_50V8J  [C_0402]  106.05 20.19 270 top
CE3  0.1U_0402_25V6  [C_0402]  29.51 17.73 180 bottom
CE4  10U_0603_6.3V6M  [C_0603]  29.75 14.17 180 bottom
CE10  0.1U_0402_25V6  [C_0402]  29.51 18.62 180 bottom
CE13  0.047U_0402_16V4Z  [C_0402]  184.62 72.9 90 top
CE14  1U_0402_6.3V6K  [C_0402]  183.74 72.9 90 top
CE17  1U_0402_6.3V6K  [C_0402]  182.08 58.45 270 top
CE21  1U_0402_6.3V6K  [C_0402]  192.24 61.37 270 top
CE22  1U_0402_6.3V6K  [C_0402]  192.24 57.3 270 top
CE38  0.1U_0402_25V6  [C_0402]  189.76 66.75 0 top
CE39  2200P_0402_50V7K  [C_0402]  190.09 71.25 90 top
CE40  0.1U_0402_25V6  [C_0402]  179.42 57.53 90 top
CE41  0.1U_0402_25V6  [C_0402]  175.05 65.48 180 top
CE42  10U_0603_6.3V6M  [C_0603]  174.27 73.61 0 top
CE43  0.1U_0402_25V6  [C_0402]  174.79 69.93 180 top
CE44  0.1U_0402_25V6  [C_0402]  184.57 64.18 90 bottom
CE45  4.7U_0603_6.3V6K  [C_0603]  193.31 62.19 270 bottom
CE46  0.1U_0402_25V6  [C_0402]  181.7 73.03 90 top
CE47  100P_0402_50V8J  [C_0402]  134.65 59.65 270 top
CE48  100P_0402_50V8J  [C_0402]  95.6 43.69 90 bottom
CE49  1U_0402_6.3V6K  [C_0402]  189.58 60.45 90 top
CE50  0.1U_0402_25V6  [C_0402]  176.1 59.01 0 top
CE51  100P_0402_50V8J  [C_0402]  190.03 74.5 180 top
CE52  4.7P_0402_50V8C  [C_0402]  180.81 73.94 270 top
CE53  27P_0402_50V8J  [C_0402]  187.6 58.37 0 top
CE54  4700P_0402_25V7K  [C_0402]  189.76 65.86 0 top
CE55  0.1U_0402_25V6  [C_0402]  187.29 72.9 90 top
CE56  1U_0402_6.3V6K  [C_0402]  189.58 56.39 90 top
CE57  100P_0402_50V8J  [C_0402]  53.36 51.26 0 bottom
CE58  2200P_0402_50V7K  [C_0402]  190.09 68.61 270 top
CE59  1U_0402_6.3V6K  [C_0402]  173.02 64.47 180 top
CE60  2200P_0402_50V7K  [C_0402]  190.03 73.61 180 top
CE61  0.1U_0402_25V6  [C_0402]  178.02 73.03 90 top
CE62  22P_0402_50V8J  [C_0402]  184.95 58.37 180 top
CE63  0.1U_0402_25V6  [C_0402]  182.85 72.9 90 top
CE64  0.1U_0402_25V6  [C_0402]  182.97 58.45 270 top
CE65  0.1U_0402_25V6  [C_0402]  189.58 59.46 270 top
CE66  100P_0402_50V8J  [C_0402]  155.67 40.51 90 top
CE67  2200P_0402_50V7K  [C_0402]  190.09 70.38 270 top
CE68  47P_0402_50V8J~D  [C_0402]  175.05 61.16 180 top
CH1  0.1U_0402_25V6K~D  [C_0402]  65.37 78.68 90 top
CH2  15P_0402_50V8J~D  [C_0402]  167.8 52.77 90 bottom
CH3  15P_0402_50V8J~D  [C_0402]  167.8 50.13 270 bottom
CH4  1U_0402_6.3V6K~D  [C_0402]  157.75 51.26 0 bottom
CH5  1U_0402_6.3V6K~D  [C_0402]  157.75 50.31 0 bottom
CH6  .1U_0402_16V7K~D  [C_0402]  174.44 48.37 270 bottom
CH7  .1U_0402_16V7K~D  [C_0402]  189.7 59.82 90 bottom
CH11  0.1U_0402_10V7K~D  [C_0402]  136.54 77.61 270 bottom
CH16  0.1U_0402_10V7K~D  [C_0402]  135.65 77.61 270 bottom
CH23  15P_0402_50V8J~D  [C_0402]  133.95 77.18 270 top
CH24  15P_0402_50V8J~D  [C_0402]  133.95 78.04 90 top
CH25  0.1U_0402_10V7K~D  [C_0402]  134.95 75.38 270 bottom
CH26  0.1U_0402_10V7K~D  [C_0402]  134.07 75.38 270 bottom
CH36  100U_A1_6.3VM_R70M  [C_A1]  168.32 45.35 0 bottom
CH39  1U_0402_6.3V6K~D  [C_0402]  146.47 65.72 270 top
CH40  1U_0402_6.3V6K~D  [C_0402]  144.27 66.47 180 top
CH41  1U_0402_6.3V6K~D  [C_0402]  149.87 72.63 270 top
CH47  0.1U_0402_10V7K~D  [C_0402]  146.41 61.24 180 top
CH61  100U_A1_6.3VM_R70M  [C_A1]  168.31 47.62 0 bottom
CH62  100U_A1_6.3VM_R70M  [C_A1]  173.5 55.76 270 bottom
CH65  100U_A1_6.3VM_R70M  [C_A1]  171.02 55.58 180 bottom
CH82  0.1U_0402_10V7K~D  [C_0402]  146.19 57.36 270 top
CH83  0.1U_0402_10V7K~D  [C_0402]  155.81 50.53 0 bottom
CH84  1U_0402_6.3V6K~D  [C_0402]  155.81 49.64 0 bottom
CH85  1U_0402_6.3V6K~D  [C_0402]  142.93 57.05 90 top
CH95  1U_0402_6.3V6K~D  [C_0402]  15.64 10.75 0 top
CH102  10P_0402_50V8J~D  [C_0402]  163.83 60.15 180 bottom
CH1204  22U_0603_6.3V6M~D  [C_0603]  136.62 41.84 180 top
CH1205  1U_0402_6.3V6K~D  [C_0402]  138.71 59.31 90 top
CH1206  0.1U_0402_10V7K  [C_0402]  149.78 59.41 0 top
CH1207  1U_0402_6.3V6K~D  [C_0402]  143.9 56.1 270 top
CH1213  1U_0402_6.3V6K~D  [C_0402]  140.18 61.33 270 top
CH1214  1U_0402_6.3V6K~D  [C_0402]  143.72 68.75 180 top
CH1215  1U_0402_6.3V6K~D  [C_0402]  142.14 66.77 270 top
CH1216  1U_0402_6.3V6K~D  [C_0402]  146.39 59.46 180 top
CH1217  10U_0603_6.3V6M~D  [C_0603]  140.3 57.8 90 top
CH1218  1U_0402_6.3V6K~D  [C_0402]  141.51 50.48 90 top
CH1219  1U_0402_6.3V6K~D  [C_0402]  143.95 64.35 0 top
CH1220  22U_0603_6.3V6M~D  [C_0603]  141.7 59.2 90 top
CH1221  1U_0402_6.3V6K~D  [C_0402]  144.2 57.76 0 top
CH1222  1U_0402_6.3V6K~D  [C_0402]  144.3 59.18 90 top
CH1223  22U_0603_6.3V6M~D  [C_0603]  143.22 59.2 90 top
CH1224  1U_0402_6.3V6K~D  [C_0402]  145.69 55.46 270 top
CH1225  22U_0603_6.3V6M~D  [C_0603]  151.69 59.74 270 top
CH1226  0.1U_0402_10V7K  [C_0402]  143.03 64.93 180 top
CH1227  1U_0402_6.3V6K~D  [C_0402]  146.4 62.99 180 top
CH1229  1U_0402_6.3V6K~D  [C_0402]  140.36 66.77 270 top
CH1231  1U_0402_6.3V6K~D  [C_0402]  140.12 74.5 180 bottom
CH1232  1U_0402_6.3V6K~D  [C_0402]  146.41 60.35 180 top
CH1233  1U_0402_6.3V6K~D  [C_0402]  141.63 57.81 270 top
CH1234  1U_0402_6.3V6K~D  [C_0402]  141.25 66.77 270 top
CH1235  1U_0402_6.3V6K~D  [C_0402]  138.82 64.06 270 top
CH1236  0.1U_0402_25V6K~D  [C_0402]  94.96 74.3 90 bottom
CH1239  10U_0603_6.3V6M~D  [C_0603]  142.69 70.91 180 top
CH1241  0.1U_0402_10V7K~D  [C_0402]  114.14 75.5 90 bottom
CH1242  15P_0402_50V8J  [C_0402]  149.46 45.1 180 bottom
CH1243  15P_0402_50V8J  [C_0402]  144.37 51.08 270 top
CH1244  15P_0402_50V8J  [C_0402]  143.67 46.23 90 top
CH1245  15P_0402_50V8J  [C_0402]  173.53 48.37 270 bottom
CH1246  15P_0402_50V8J  [C_0402]  150.51 69.86 0 top
CH1247  15P_0402_50V8J  [C_0402]  140.99 75.07 0 top
CH1248  15P_0402_50V8J  [C_0402]  145.67 74.19 270 top
CH1249  15P_0402_50V8J  [C_0402]  188.82 59.82 90 bottom
CLRP1  SHORT PADS  [SHORTPADS]  158.28 52.34 0 bottom
CS42  0.1U_0402_10V7K  [C_0402]  187.11 36.02 180 bottom
CS43  0.1U_0402_10V7K  [C_0402]  187.11 35.13 180 bottom
CS44  0.1U_0402_10V7K  [C_0402]  185.51 37.47 90 top
CS57  0.1U_0402_10V7K  [C_0402]  187.11 31.45 180 bottom
CS58  0.1U_0402_10V7K  [C_0402]  187.11 30.56 180 bottom
CS59  0_0402_5%~D  [R_0402]  187.11 29.41 180 bottom
CS60  0_0402_5%~D  [R_0402]  187.11 28.53 180 bottom
CS61  0_0402_5%~D  [R_0402]  187.11 33.48 180 bottom
CS62  0_0402_5%~D  [R_0402]  187.11 32.59 180 bottom
CV1  10U_0603_6.3V6M~D  [C_0603]  19.3 64.75 90 bottom
CV2  .1U_0402_16V7K~D  [C_0402]  18.23 64.94 90 bottom
CV3  .1U_0402_16V7K~D  [C_0402]  19.7 57.23 0 bottom
CV4  .1U_0402_16V7K~D  [C_0402]  19.7 58.12 0 bottom
CV5  .1U_0402_16V7K~D  [C_0402]  19.37 60.53 0 top
CV6  .1U_0402_16V7K~D  [C_0402]  19.7 59.01 0 bottom
CV7  .1U_0402_16V7K~D  [C_0402]  19.37 61.42 0 top
CV8  0.1U_0402_10V7K~D  [C_0402]  18.64 67.11 270 top
CV9  .1U_0402_16V7K~D  [C_0402]  19.7 59.89 0 bottom
CV10  0.1U_0402_10V7K~D  [C_0402]  21.28 67.13 270 top
CV11  .1U_0402_16V7K~D  [C_0402]  19.37 62.31 0 top
CV12  .1U_0402_16V7K~D  [C_0402]  19.37 63.2 0 top
CV13  0.1U_0402_10V6K~D  [C_0402]  17.8 76.05 0 top
CV14  0.1U_0402_10V7K~D  [C_0402]  17.32 64.96 90 bottom
CV15  22U_0805_6.3V6M~D  [C_0805]  22.47 63.08 270 bottom
CV798  15P_0402_50V8J  [C_0402]  19.52 67.1 270 top
D72  BAT54CW-7-F_SOT323-3~D  [BAT54CW-7-F_SOT323-3]  194.85 30.94 90 top
D73  BAT54CW-7-F_SOT323-3~D  [BAT54CW-7-F_SOT323-3]  194.85 28.53 90 top
D81  -  [RB751S40T1G_SOD523-2]  165.57 17.23 0 top
D93  BAT54CW-7-F_SOT323-3~D  [BAT54CW-7-F_SOT323-3]  203.04 39.39 180 top
D116  BAT54CW-7-F_SOT323-3~D  [BAT54CW-7-F_SOT323-3]  40.74 37.58 90 top
D122  -  [BAS40-04_SOT23-3]  11.88 10.62 270 top
DA1  AZ5125-02S.R7G_SOT23-3  [AZ5125-02SPR7G_SOT23-3]  17.29 34.33 0 bottom
DA2  AZ5125-02S.R7G_SOT23-3  [AZ5125-02SPR7G_SOT23-3]  17.8 23.56 180 bottom
DA3  -  [PJDLC05C_SOT23-3]  19.04 15.92 270 top
DA4  -  [PJDLC05C_SOT23-3]  26.56 15.71 90 top
DA5  AZ5123-01F.R7G_DFN1006P2X2  [ESD207-B1-02EL_TSLP-2-19-2]  6.6 23.59 270 top
DA6  -  [BAT54A-7-F_SOT23-3]  22.73 26.29 0 bottom
DA7  AZ5123-01F.R7G_DFN1006P2X2  [ESD207-B1-02EL_TSLP-2-19-2]  9.55 23.2 90 bottom
DI1  TVWDF1004AD0_DFN9  [IP4292CZ10-TBR_XSON10_2P5X1]  18.36 46.24 90 bottom
DI2  -  [L30ESDL5V0C3-2_SOT23-3]  19.25 39.73 90 bottom
DI3  -  [L30ESDL5V0C3-2_SOT23-3]  62.16 68.64 180 bottom
DI4  -  [L30ESDL5V0C3-2_SOT23-3]  66.32 68.64 180 bottom
DZ1  -  [RB751S40T1G_SOD523-2]  46.58 42.71 90 top
DZ2  -  [RB751S40T1G_SOD523-2]  45.43 42.71 90 top
DZ3  -  [RB751S40T1G_SOD523-2]  193.51 54.63 270 top
DZ4  -  [RB751S40T1G_SOD523-2]  192.37 54.63 270 top
FD1  FIDUCAL  [FIDUCIAL_C40M80]  20.63 77.55 0 top
FD2  FIDUCIAL  [FIDUCIAL_C40M80]  20.63 77.55 180 bottom
FD3  FIDUCAL  [FIDUCIAL_C40M80]  209.64 14.94 0 top
FD4  FIDUCIAL  [FIDUCIAL_C40M80]  211.42 21.04 180 bottom
H1  -  [H_2P0]  10.7 70.12 0 top
H3  -  [H_1P8N]  6.2 17.12 0 top
H4  -  [H_2P0]  10.7 17.12 0 top
H6  -  [H_3P3]  41 72.3 0 top
H7  -  [H_2P0]  53.39 13.31 0 top
H9  -  [H_2P0]  82.46 79.8 0 top
H10  -  [H_3P3]  104.5 74.85 0 top
H11  -  [H_3P3]  104.5 53.85 0 top
H12  -  [H_2P0]  110.54 13.31 0 top
H13  -  [H_2P0]  129.59 13.28 0 top
H14  -  [H_3P3]  163.3 74.85 0 top
H15  -  [H_3P3]  163.3 53.85 0 top
H16  -  [H_3P3]  188.7 23.12 0 top
H17  -  [H_3P3]  203.5 50.12 0 top
H18  -  [H_2P0]  215.31 15.47 0 top
H19  -  [H_2P0]  183.32 79.8 0 top
H20  -  [EMIST_SUL-12A2M_1P]  19 53.62 180 bottom
H21  -  [EMIST_SUL-12A2M_1P]  19 36.62 180 bottom
H22  -  [EMIST_SUL-12A2M_1P]  27.9 44.92 270 bottom
H23  -  [H_2P3X1P8N]  200.17 79.8 0 top
H24  -  [EMIST_SUL-12A2M_1P]  10.2 36.86 0 top
H25  -  [EMIST_SUL-12A2M_1P]  10.2 53.36 0 top
H26  -  [H_3P2X0P8]  98.1 14.4 180 bottom
JAPS  ACES_50506-01841-P01  [ACES_50506-01841-P01_18P]  199.43 35.44 270 bottom
JBATT1  FOX_GS73091-10272-7H  [FOX_GS73091-10272-7H_9P-T]  71.6 26.14 0 bottom
JCAM  CVILU_CI1806M2HRP-NH  [CVILU_CI1806M2HRP-NH_6P]  54.6 72.62 0 bottom
JDEG1  HB_A531015-SCHR21  [HB_A531015-SCHR21_10P]  170.16 68.22 0 bottom
JEDP  ACES_50398-04041-001  [ACES_50398-04041-001_40P]  193.1 24.37 90 bottom
JFAN1  ACES_50224-00401-001  [ACES_50224-00401-001_4P]  166.12 18.37 270 bottom
JHP1  SINGA_2SJ3095-022111F  [SINGA_2SJ3095-022111F_6P-T]  12.32 25.51 270 bottom
JIO1  JXT_FP270H-061G1AM  [JXT_FP270H-061G1AM_61P]  210.7 15.54 180 bottom
JKB1  E-T_6710K-Y15M-31L  [E-T_6710K-Y15M-31L_15P]  47.42 20.31 180 bottom
JLPDE1  HB_A531015-SCHR21  [HB_A531015-SCHR21_10P]  180.15 71.22 0 bottom
JMDP  TE_C-PT13-061  [TE_C-PT13-061_20P-T]  10.84 57.87 90 bottom
JNFC1  E-T_6705K-Y15N-00L  [E-T_6705K-Y15N-00L_15P]  88.33 20.9 180 bottom
JNGFF1  CONCR_213EBAA2FKA  [CONCR_213EBAA2FKA_67P]  31.75 38.77 0 bottom
JNGFF3  CONCR_213MAAA32FA  [CONCR_213MAAA32FA_67P-T]  183.65 23.29 90 bottom
JP100  ACES_88266-05001  [ACES_88266-05001_5P]  27.97 71.3 90 bottom
JPA1  -  [JUMP_43X39]  31.21 31.27 270 bottom
JPA2  -  [JUMP_43X39]  28.34 26.62 0 bottom
JPA3  -  [JUMP_43X39]  23.72 21.39 270 bottom
JPA4  -  [JUMP_43X39]  4.76 22.7 180 bottom
JPA5  -  [JUMP_43X39]  27.58 29.86 0 bottom
JRTC1  ACES_50278-00201-001  [ACES_50278-00201-001_2P]  15.04 10.61 116.9 bottom
JSPK1  ACES_50224-00401-001  [ACES_50224-00401-001_4P]  26.29 13.81 90 bottom
JTAG1  @SHORT PADS~D  [SHORTPADS]  172.56 66.5 180 top
JTP1  E-T_6705K-Y08N-40L  [E-T_6705K-Y08N-40L_8P]  187.15 19.49 180 bottom
JTS  CVILU_CI1806M2HRP-NH  [CVILU_CI1806M2HRP-NH_6P]  72.14 74.56 90 bottom
JUSB1  TE_C-PT13-067  [TE_C-PT13-067_9P-T]  14.72 48.61 90 bottom
JXDP  SAMTE_BSH-030-01-L-D-A  [SAMTE_BSH-030-01-L-D-A_60P]  75.41 76.22 180 top
L2  BLM15PX181SN1D_2P  [MURAT_BLM15PX181SN1D_2P]  28.7 21.1 180 top
L3  BLM15PX181SN1D_2P  [MURAT_BLM15PX181SN1D_2P]  28.7 19.32 180 top
L4  BLM15PX181SN1D_2P  [MURAT_BLM15PX181SN1D_2P]  30.76 20.55 270 top
L5  BLM15PX181SN1D_2P  [MURAT_BLM15PX181SN1D_2P]  32.41 20.55 270 top
L55  DLW21HN900HQ2L_4P  [MURAT_DLW21HN900HQ2L_4P]  70.68 67.18 180 bottom
L56  HCM1012GH900BP_4P  [INPAQ_HCM1012GH900BP_4P]  196.88 39.45 180 top
L57  HCM1012GH900BP_4P  [INPAQ_HCM1012GH900BP_4P]  196.88 37.55 180 top
L58  HCM1012GH900BP_4P  [INPAQ_HCM1012GH900BP_4P]  196.96 35.64 180 top
L59  HCM1012GH900BP_4P  [INPAQ_HCM1012GH900BP_4P]  196.88 41.36 180 top
L60  HCM1012GH900BP_4P  [INPAQ_HCM1012GH900BP_4P]  196.88 43.26 180 top
L61  2.2UH_LQM2MPN2R2NG0L_30%  [MURAT_LQM2MPN2R2NG0L_2P]  173.64 56.38 270 top
L62  2.2UH_LQM2MPN2R2NG0L_30%  [MURAT_LQM2MPN2R2NG0L_2P]  169.11 56.09 0 top
L63  2.2UH_LQM2MPN2R2NG0L_30%  [MURAT_LQM2MPN2R2NG0L_2P]  168.58 47.71 0 top
LA1  BLM15PX600SN1D_2P  [MURAT_BLM15PX600SN1D_2P]  37.49 26.51 90 bottom
LA2  BLM15PX600SN1D_2P  [MURAT_BLM15PX600SN1D_2P]  36.29 25.08 270 bottom
LA3  BLM21PG600SN1D_0805~D  [MURAT_BLM21PG600SN1D_L0805_2P]  30.37 22.18 180 bottom
LA4  0_0402_1%  [R0402_0OHM]  11.62 23.97 270 bottom
LA5  0_0402_1%  [R0402_0OHM]  8.59 22.84 90 top
LA6  PBY100505T-700Y-N  [CHILI_PBY100505T-600Y-N_2P]  16.39 27.39 180 bottom
LA7  PBY100505T-700Y-N  [CHILI_PBY100505T-600Y-N_2P]  19.42 27.41 0 bottom
LA14  BLM15BB220SN1D_2P  [MURAT_BLM15BB220SN1D_2P]  39.14 26.24 180 top
LED10  27-11-T1D-CP1Q1RY-3C_WHITE~D  [LED_27-11-T1D-CP1Q1RY-3C_2P]  2.5 8.4 90 top
LED11  27-11-T1D-CP1Q1RY-3C_WHITE~D  [LED_27-11-T1D-CP1Q1RY-3C_2P]  2.5 4.8 90 top
LED12  27-11-T1D-CP1Q1RY-3C_WHITE~D  [LED_27-11-T1D-CP1Q1RY-3C_2P]  2.5 15.6 90 top
LED13  27-11-T1D-CP1Q1RY-3C_WHITE~D  [LED_27-11-T1D-CP1Q1RY-3C_2P]  2.5 1.2 90 top
LED14  27-11-T1D-CP1Q1RY-3C_WHITE~D  [LED_27-11-T1D-CP1Q1RY-3C_2P]  2.5 12 90 top
LH10  2.2UH_LQM2MPN2R2NG0L_30%  [MURAT_LQM2MPN2R2NG0L_2P]  142.24 78.37 180 top
LH11  2.2UH_LQM2MPN2R2NG0L_30%  [MURAT_LQM2MPN2R2NG0L_2P]  147.29 78.6 270 top
LH12  2.2UH_LQM2MPN2R2NG0L_30%  [MURAT_LQM2MPN2R2NG0L_2P]  170.18 45.35 180 top
MC3  680P_0402_50V7K~D  [C_0402]  193.21 28.4 180 top
MC29  12P_0402_50V8J~D  [C_0402]  155.73 59.88 180 bottom
MC30  22P_0402_50V8J~D  [C_0402]  177.56 44.87 0 bottom
MC31  10P_0402_50V8J~D  [C_0402]  157.66 44.1 270 top
MC32  22P_0402_50V8J~D  [C_0402]  185.63 50.61 90 bottom
MC33  22P_0402_50V8J~D  [C_0402]  181.34 52.09 90 bottom
MD5  -  [TVWDF1004AD0_DFN9]  17.11 61.91 270 top
MD9  -  [PESD5V0U2BT_SOT23-3]  182.29 14.83 0 top
MD10  -  [PESD5V0U2BT_SOT23-3]  188.09 14.55 0 top
MD16  -  [TVWDF1004AD0_DFN9]  18.18 59.5 270 bottom
ML9  DLW21HN900HQ2L_4P  [MURAT_DLW21HN900HQ2L_4P]  70.99 70.07 180 bottom
ML10  DLW21HN900HQ2L_4P  [MURAT_DLW21HN900HQ2L_4P]  31.26 36.76 0 bottom
ML11  DLW21HN900HQ2L_4P  [MURAT_DLW21HN900HQ2L_4P]  25.35 39.1 180 bottom
ML12  CMMI21T-670Y-N  [MURAT_DLW21SN670HQ2L_4P]  22.98 50.48 180 bottom
ML13  CMMI21T-670Y-N  [MURAT_DLW21SN670HQ2L_4P]  23.49 46.67 180 bottom
NOREF  -  []  102.33 77.83 0 top
NOREF#2  -  []  183.32 79.8 0 top
NOREF#3  -  []  139.61 14.81 0 top
NOREF#4  -  []  215.31 15.47 0 top
NOREF#5  -  []  129.59 13.28 0 top
NOREF#6  -  []  163.3 74.85 0 top
NOREF#7  -  []  54.73 123.85 0 top
NOREF#8  -  []  61.57 60.56 0 top
NOREF#9  -  []  203.5 50.12 0 top
NOREF#10  -  []  163.3 53.85 0 top
NOREF#11  -  []  188.7 23.12 0 top
NOREF#12  -  []  41 72.3 0 top
NOREF#13  -  []  96.87 -27.07 0 top
NOREF#14  -  []  10.7 17.12 0 top
NOREF#15  -  []  95.53 45 0 top
NOREF#16  -  []  82.46 79.8 0 top
NOREF#17  -  []  104.5 74.85 0 top
NOREF#18  -  []  104.5 53.85 0 top
NOREF#19  -  []  61.05 15.13 0 top
NOREF#20  -  []  110.54 13.31 0 top
NOREF#21  -  []  53.39 13.31 0 top
NOREF#22  -  []  10.7 70.12 0 top
NOREF#23  -  []  142.56 39.93 180 bottom
NOREF#24  -  []  172.24 24.66 180 bottom
NOREF#25  -  []  122.27 39.23 180 bottom
NOREF#26  -  []  153.12 35.31 180 bottom
PC51  0.47U_0603_16V7K  [C_0603]  24.6 66.05 90 top
PC100  0.01U_0402_25V7K  [C_0402]  73.39 32.18 0 bottom
PC101  1000P_0402_50V7K  [C_0402]  73.4 31.21 0 bottom
PC102  2200P_0402_50V7K  [C_0402]  74.31 30.32 180 bottom
PC103  1000P_0603_50V7K  [C_0603]  26 76.46 90 top
PC104  1000P_0402_50V7K  [C_0402]  26 74.19 270 top
PC105  100P_0402_50V8J  [C_0402]  26.89 74.19 270 top
PC106  1000P_0402_50V7K  [C_0402]  53.1 32.64 270 bottom
PC107  100P_0402_50V8J  [C_0402]  35.32 77.66 90 top
PC108  10U_0805_25V6K  [C_0805]  36.66 76.91 90 top
PC109  1U_0603_10V6K  [C_0603]  48.35 76.98 90 bottom
PC110  0.1U_0402_25V6  [C_0402]  37.18 75.59 270 top
PC200  0.022U_0603_50V7K  [C_0603]  44.34 28.32 90 bottom
PC201  0.1U_0402_25V6  [C_0402]  45.79 32.41 180 bottom
PC202  1U_0603_25V6K  [C_0603]  49.24 30.88 180 bottom
PC203  0.1U_0402_25V6  [C_0402]  46.51 30.67 90 top
PC204  0.1U_0402_25V6  [C_0402]  47.77 31.95 0 bottom
PC205  1U_0603_10V6K  [C_0603]  51.27 34.05 90 top
PC206  1U_0805_25V6K  [C_0805]  46.31 31.09 180 bottom
PC207  0.1U_0402_25V6  [C_0402]  48.68 28.91 180 bottom
PC208  10U_0805_25V6K  [C_0805]  57.08 34.88 180 top
PC209  10U_0805_25V6K  [C_0805]  57.08 34.88 180 bottom
PC210  0.047U_0603_25V7M  [C_0603]  48.86 35.45 270 top
PC211  2200P_0402_50V7K  [C_0402]  57.13 33.54 180 top
PC212  10U_0805_25V6K  [C_0805]  57.08 36.65 180 top
PC213  10U_0805_25V6K  [C_0805]  57.08 36.65 180 bottom
PC214  10U_0805_25V6K  [C_0805]  67.11 36.98 180 bottom
PC215  10U_0805_25V6K  [C_0805]  67.11 38.69 180 bottom
PC216  100P_0402_50V8J  [C_0402]  47.91 27.9 270 bottom
PC217  100P_0402_50V8J  [C_0402]  48.8 27.9 270 bottom
PC218  100P_0402_50V8J  [C_0402]  49.69 27.9 270 bottom
PC219  0.1U_0603_25V7K  [C_0603]  67.67 36.06 180 top
PC220  10U_0805_25V6K  [C_0805]  70.2 40.67 90 bottom
PC221  10U_0805_25V6K  [C_0805]  71.94 40.67 90 bottom
PC222  10U_0805_25V6K  [C_0805]  73.69 40.67 90 bottom
PC223  1U_0603_25V6K  [C_0603]  52.35 28.91 180 bottom
PC224  1000P_0603_50V7K  [C_0603]  57.43 28.97 90 top
PC225  0.1U_0402_25V6  [C_0402]  50.94 30.88 0 bottom
PC226  0.1U_0402_25V6  [C_0402]  53.76 31.5 270 top
PC227  0.1U_0402_25V6  [C_0402]  51.86 29.99 180 bottom
PC228  0.1U_0603_25V7K  [C_0603]  65.44 42.28 180 top
PC229  0.1U_0603_25V7K  [C_0603]  65.43 41.08 180 top
PC230  0.1U_0603_25V7K  [C_0603]  65.42 39.86 180 top
PC231  10U_0805_25V6K  [C_0805]  57.08 38.43 180 bottom
PC232  10U_0805_25V6K  [C_0805]  57.08 38.43 180 top
PC233  10U_0805_25V6K  [C_0805]  63.57 41.83 270 bottom
PC234  10U_0805_25V6K  [C_0805]  65.3 41.83 270 bottom
PC235  10U_0805_25V6K  [C_0805]  67.98 34.41 180 top
PC236  10U_0805_25V6K  [C_0805]  67.99 30.74 180 top
PC237  10U_0805_25V6K  [C_0805]  67.98 32.51 180 top
PC300  4.7U_0603_6.3V6K  [C_0603]  56.29 54.88 180 bottom
PC302  1000P_0402_50V7K  [C_0402]  29.3 63.76 90 top
PC303  2200P_0402_50V7K  [C_0402]  70.51 56.52 90 bottom
PC305  0.1U_0402_25V6  [C_0402]  58.7 58.93 90 bottom
PC306  0.1U_0402_25V6  [C_0402]  59.4 50.23 90 bottom
PC307  150U_B2_6.3VM_R35M  [C_B2]  57.22 61.99 0 bottom
PC308  150U_B2_6.3VM_R35M  [C_B2]  56.94 43.58 0 bottom
PC309  680P_0603_50V8J  [C_0603]  63.59 59.26 270 bottom
PC310  680P_0603_50V8J  [C_0603]  61.69 50.18 90 bottom
PC311  4.7U_0603_6.3V6K  [C_0603]  62.83 54.62 270 bottom
PC312  4.7U_0603_6.3V6M  [C_0603]  57.43 58.18 90 bottom
PC313  10U_0805_25V6K  [C_0805]  69.18 56.5 90 bottom
PC314  0.1U_0402_25V6  [C_0402]  63.61 55.97 90 bottom
PC315  10U_0805_25V6K  [C_0805]  64.38 54.64 270 bottom
PC323  0.1U_0402_25V6  [C_0402]  28.16 58.45 270 top
PC324  1U_0603_10V6K  [C_0603]  25.87 67.45 270 top
PC400  0.1U_0402_25V6  [C_0402]  192.67 71.85 180 bottom
PC401  10U_0805_25V6K  [C_0805]  193.08 64.97 0 top
PC402  22P_0402_50V8J  [C_0402]  195.34 74.76 270 top
PC403  22U_0805_6.3VAM  [C_0805]  198.15 75.33 180 top
PC404  0.1U_0402_25V6  [C_0402]  192.96 66.43 0 top
PC405  2200P_0402_50V7K  [C_0402]  192.96 67.38 0 top
PC406  3300P_0402_50V7-K  [C_0402]  190.97 73.87 0 top
PC407  680P_0402_50V7K  [C_0402]  196.79 64.83 180 top
PC408  0.1U_0402_25V6  [C_0402]  38.59 65.86 180 top
PC409  10U_0805_25V6K  [C_0805]  34.57 63.65 270 top
PC410  22P_0402_50V8J  [C_0402]  43.1 62.12 180 top
PC411  22U_0805_6.3VAM  [C_0805]  39.82 58.18 90 top
PC412  0.1U_0402_25V6  [C_0402]  34.98 64.86 180 top
PC413  2200P_0402_50V7K  [C_0402]  35.94 64.35 270 top
PC414  3300P_0402_50V7-K  [C_0402]  42.19 65.69 270 top
PC415  680P_0402_50V7K  [C_0402]  34.08 60.93 0 top
PC428  100P_0402_50V8J  [C_0402]  24.1 60.33 90 top
PC429  0.01UF_0402_25V7K  [C_0402]  23.21 73.28 90 top
PC433  0.1U_0402_10V7K  [C_0402]  24.1 73.28 90 top
PC434  0.1U_0402_10V7K  [C_0402]  24.99 73.28 90 top
PC500  0.22U_0402_10V6K  [C_0402]  203.6 61.29 0 top
PC502  680P_0603_50V7K  [C_0603]  201.2 59.89 180 top
PC503  2200P_0402_50V7K  [C_0402]  197.39 64.84 90 bottom
PC504  0.1U_0402_25V6  [C_0402]  198.28 64.84 90 bottom
PC505  0.1U_0603_25V7K  [C_0603]  200.56 63.32 270 top
PC506  10U_0805_25V6K  [C_0805]  197.82 63.25 270 bottom
PC507  10U_0805_25V6K  [C_0805]  197.83 63.26 270 top
PC509  22U_0805_6.3VAM  [C_0805]  195 57.67 180 bottom
PC510  22U_0805_6.3VAM  [C_0805]  195 54.24 180 bottom
PC511  22U_0805_6.3VAM  [C_0805]  195 59.39 180 bottom
PC512  22U_0805_6.3VAM  [C_0805]  195 55.96 180 bottom
PC513  4.7U_0603_6.3V6K  [C_0603]  203.36 66.88 0 bottom
PC514  4.7U_0603_6.3V6K  [C_0603]  201.45 65.93 180 bottom
PC515  22P_0402_50V8J  [C_0402]  204.51 65.74 180 bottom
PC600  0.1U_0402_25V6  [C_0402]  84.18 54.69 180 bottom
PC601  2200P_0402_50V7K  [C_0402]  84.18 54.69 180 top
PC602  10U_0805_25V6K  [C_0805]  84.83 53.35 180 top
PC603  10U_0805_25V6K  [C_0805]  84.83 53.35 180 bottom
PC604  0.1U_0603_25V7K  [C_0603]  77.56 52.02 180 bottom
PC605  10U_0805_6.3V6K  [C_0805]  76.03 45.51 180 bottom
PC606  10U_0805_6.3V6K  [C_0805]  76.03 43.79 180 bottom
PC607  1U_0603_10V6K  [C_0603]  71.53 51.83 0 bottom
PC609  330U_B_2.5VM_R9M  [C_B]  92.55 39.35 90 bottom
PC610  0.033U_0402_16V7K  [C_0402]  72.55 44.97 270 bottom
PC611  1U_0603_10V6K  [C_0603]  72.9 52.03 0 top
PC612  680P_0402_50V7K  [C_0402]  77.06 52.97 0 top
PC613  0.1U_0402_10V7K  [C_0402]  71.65 49.04 0 top
PC614  0.1U_0402_10V7K  [C_0402]  71.65 48.15 0 top
PC617  330U_B2_2.5VM_R9M  [C_B2]  87.95 44.54 270 bottom
PC700  4700P_0402_25V7K  [C_0402]  76.8 65.28 90 bottom
PC701  0.01U_0402_16V7K  [C_0402]  77.69 65.28 90 bottom
PC702  10U_0805_16V6K  [C_0805]  88.27 56.02 0 bottom
PC703  10U_0805_16V6K  [C_0805]  88.16 55.02 0 top
PC704  100U_D2_16VM_R50M  [C_D2]  84.8 57.2 90 bottom
PC705  0.1U_0402_25V6  [C_0402]  90.89 54.57 90 top
PC706  2200P_0402_50V7K  [C_0402]  90.06 54.62 0 bottom
PC707  0.1U_0402_25V6  [C_0402]  85.04 61.55 0 top
PC708  1U_0603_10V6K  [C_0603]  73.18 60.02 270 bottom
PC709  100P_0402_50V8J  [C_0402]  81.83 59.13 180 bottom
PC710  1U_0603_10V6K  [C_0603]  91.53 59.7 90 top
PC711  680P_0603_50V7K  [C_0603]  91.53 57.29 90 top
PC712  1500P_0402_50V7K  [C_0402]  80.93 56.45 90 bottom
PC713  0.33U_0603_10V7K  [C_0603]  78.96 57.16 270 bottom
PC714  1U_0603_10V6K  [C_0603]  77.75 57.16 270 bottom
PC715  .047U_0402_16V7K  [C_0402]  81.44 63.02 270 bottom
PC716  .047U_0402_16V7K  [C_0402]  80.55 63.02 270 bottom
PC717  0.1U_0402_25V6  [C_0402]  72.8 54.1 90 bottom
PC718  47P_0402_50V8J  [C_0402]  76.12 57.12 180 top
PC800  22U_0805_6.3V6M  [C_0805]  128.27 63.69 0 top
PC801  22U_0805_6.3V6M  [C_0805]  124.86 63.71 0 top
PC802  22U_0805_6.3V6M  [C_0805]  131.49 65.47 0 top
PC803  22U_0805_6.3V6M  [C_0805]  121.29 69.26 90 top
PC804  22U_0805_6.3V6M  [C_0805]  124.87 65.44 0 top
PC805  22U_0805_6.3V6M  [C_0805]  124.84 67.18 0 top
PC806  22U_0805_6.3V6M  [C_0805]  128.8 69.26 90 top
PC807  22U_0805_6.3V6M  [C_0805]  91.68 67.53 90 bottom
PC808  22U_0805_6.3V6M  [C_0805]  134.7 65.44 0 top
PC809  22U_0805_6.3V6M  [C_0805]  123.67 69.3 90 top
PC810  22U_0805_6.3V6M  [C_0805]  126.36 69.31 90 top
PC811  22U_0805_6.3V6M  [C_0805]  128.23 65.42 0 top
PC812  22U_0805_6.3V6M  [C_0805]  134.7 63.71 0 top
PC813  22U_0805_6.3V6M  [C_0805]  121.49 63.73 0 top
PC814  22U_0805_6.3V6M  [C_0805]  121.49 65.46 0 top
PC815  22U_0805_6.3V6M  [C_0805]  121.46 67.2 0 top
PC816  22U_0805_6.3V6M  [C_0805]  131.48 63.72 0 top
PC817  22U_0805_6.3V6M  [C_0805]  118.17 63.72 0 top
PC818  22U_0805_6.3V6M  [C_0805]  118.17 65.46 0 top
PC819  22U_0805_6.3V6M  [C_0805]  118.15 67.18 0 top
PC820  22U_0805_6.3V6M  [C_0805]  97.38 67.55 90 bottom
PC821  22U_0805_6.3V6M  [C_0805]  93.57 67.55 90 bottom
PC822  22U_0805_6.3V6M  [C_0805]  95.47 67.55 90 bottom
PC823  0.015U_0402_16V7K  [C_0402]  128.08 67.14 0 top
PD100  -  [TVNST52302AB0_SOT523-3]  66.34 26.86 270 top
PD101  -  [TVNST52302AB0_SOT523-3]  67.89 28.71 0 top
PD102  AZ5125-01H.R7G_SOD523-2  [AZ5125-01HPR7G_SOD523-2]  29.38 73.64 270 top
PD200  -  [SDMK0340L-7-F_SOD323-2]  46.79 36.38 0 bottom
PD201  -  [SDMK0340L-7-F_SOD323-2]  46.77 34.04 0 bottom
PH700  100K_0402_1%_B25/50 4250K  [R_0402]  88.56 62.43 180 bottom
PH701  10K_0402_1%_B25/50 3370K  [R_0402]  100.68 62.19 270 bottom
PJP14  PAD-OPEN1x1m  [JUMP_43X39]  29.05 15.62 90 bottom
PJP15  PAD-OPEN1x1m  [JUMP_43X39]  174.97 72.16 270 top
PJP200  PAD-OPEN1x1m  [JUMP_43X39]  51.27 26.63 270 bottom
PJP300  -  [JUMP_43X118]  55.66 46.49 90 bottom
PJP301  -  [JUMP_43X118]  56.04 64.93 90 bottom
PJP400  -  [JUMP_43X39]  197.9 76.89 90 top
PJP401  -  [JUMP_43X39]  41.38 58.43 0 top
PJP500  -  [JUMP_43X118]  196.31 51.81 270 bottom
PJP600  -  [JUMP_43X118]  82.64 40.82 270 bottom
PJP601  -  [JUMP_43X118]  87.85 40.82 270 bottom
PJP602  -  [JUMP_43X39]  75.85 41.94 270 bottom
PL100  HCB2012KF-121T50_0805  [TAI-T_HCB2012KF-121T50_2P]  70.38 31.99 270 bottom
PL101  HCB2012KF-121T50_0805  [TAI-T_HCB2012KF-121T50_2P]  72.03 31.99 270 bottom
PL102  BLM15AG102SN1D_2P  [MURAT_BLM15AG102SN1D_2P]  31.25 73.74 180 top
PL103  HCB2012KF-121T50_0805  [TAI-T_HCB2012KF-121T50_2P]  27.48 76.5 90 top
PL104  HCB2012KF-121T50_0805  [TAI-T_HCB2012KF-121T50_2P]  28.6 69.79 270 bottom
PL200  HCB2012KF-121T50_0805  [TAI-T_HCB2012KF-121T50_2P]  59.64 40.4 180 top
PL201  3.3UH_6.3A_20%_7X7X3_M  [L_7X7X3_M_2P]  61.27 32.64 0 bottom
PL300  HCB2012KF-121T50_0805  [TAI-T_HCB2012KF-121T50_2P]  68.78 54.88 180 bottom
